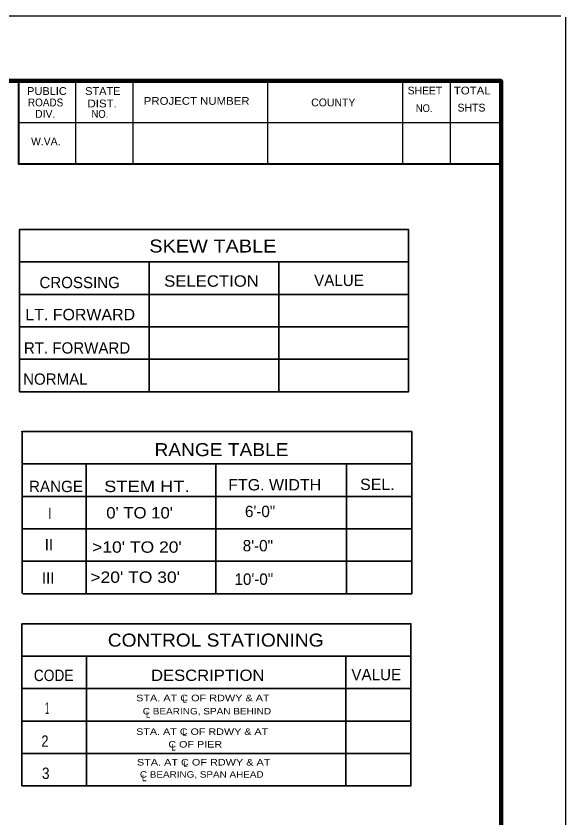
# Model space of a CAD drawing. Extents: x 1.6 to 19.9, y 2.8 to 9.5.
# Drawn here: x 19.239 to 19.901, y 8.58 to 9.545 of the extents above; entities that cross this region are included whole.
import ezdxf
from ezdxf.enums import TextEntityAlignment as Align

# ---------------------------------------------------------------- set-up
doc = ezdxf.new("R2010")
doc.units = 0
doc.header["$LTSCALE"] = 0.0047
doc.layers.add('1', color=7, linetype='Continuous', lineweight=35)

msp = doc.modelspace()

# ---------------------------------------------------------------- linework, layer by layer
at = {"layer": '1', "lineweight": 25}
for p, q in [((19.894917, 9.545083), (16.26675, 9.545083)), ((19.901167, 7.2855), (19.901167, 9.543917)), ((19.3105, 9.467), (19.3105, 9.367)), ((19.37925, 9.467), (19.37925, 9.367)), ((19.54175, 9.467), (19.54175, 9.367)), ((19.70425, 9.467), (19.70425, 9.367)), ((19.76175, 9.467), (19.76175, 9.367)), ((19.24175, 9.417), (19.823, 9.417))]:
    msp.add_line(p, q, dxfattribs=at)
at = {"layer": '1'}
for p, q in [((19.24275, 9.249), (19.7115, 9.249)), ((19.399, 9.09275), (19.399, 9.249667)), ((19.55525, 9.09275), (19.55525, 9.24875)), ((19.24275, 9.21), (19.7115, 9.21)), ((19.24275, 9.170917), (19.7115, 9.170917)), ((19.24275, 9.131833), (19.7115, 9.131833)), ((19.245917, 8.84975), (19.245917, 9.045083)), ((19.246667, 9.045), (19.715417, 9.045)), ((19.715417, 9.045), (19.715417, 8.849667)), ((19.246667, 9.005917), (19.715417, 9.005917)), ((19.323083, 8.849833), (19.323083, 9.00575)), ((19.479333, 8.850333), (19.479333, 9.00625)), ((19.636667, 8.84975), (19.636667, 9.00575)), ((19.246667, 8.966833), (19.715417, 8.966833)), ((19.246667, 8.92775), (19.715417, 8.92775)), ((19.246667, 8.88875), (19.715417, 8.88875)), ((19.7155, 8.8495), (19.24675, 8.8495)), ((19.245583, 8.61825), (19.245583, 8.8135)), ((19.245667, 8.7745), (19.714417, 8.7745)), ((19.323667, 8.61825), (19.323667, 8.774333)), ((19.636167, 8.61825), (19.636167, 8.774333)), ((19.245667, 8.735417), (19.714417, 8.735417)), ((19.245667, 8.696333), (19.714417, 8.696333)), ((19.245667, 8.65725), (19.714417, 8.65725))]:
    msp.add_line(p, q, dxfattribs=at)
at = {"layer": '1', "lineweight": 13}
msp.add_line((19.244917, 9.045), (19.713667, 9.045), dxfattribs=at)
at = {"layer": '1', "lineweight": 106}
msp.add_lwpolyline([(19.823, 7.367), (19.823, 9.467), (16.423, 9.467), (16.423, 7.367)], dxfattribs=at)
at = {"layer": '1', "lineweight": 40}
msp.add_lwpolyline([(19.24175, 9.467), (19.24175, 9.367), (19.823, 9.367)], dxfattribs=at)
at = {"layer": '1'}
msp.add_lwpolyline([(19.24275, 9.09275), (19.24275, 9.288083), (19.7115, 9.288083), (19.7115, 9.09275)], close=True, dxfattribs=at)
msp.add_lwpolyline([(19.245667, 8.8135), (19.714417, 8.8135), (19.714417, 8.61825), (19.245667, 8.61825)], dxfattribs=at)

# ---------------------------------------------------------------- texts
for s, height, width, p in [('PUBLIC', 0.009416, 1.05, (19.275958, 9.450083)), ('STATE', 0.009416, 1.05, (19.34325, 9.450083)), ('TOTAL', 0.009333, 1.1, (19.78825, 9.45075)), ('ROADS', 0.009416, 0.95, (19.274333, 9.436333)), ('DIST.', 0.009416, 1.1, (19.342458, 9.435083)), ('PROJECT NUMBER', 0.009333, 1.1, (19.456292, 9.43825)), ('NO.', 0.009416, 0.9, (19.33975, 9.422583)), ('NO.', 0.009333, 0.9, (19.730375, 9.4295))]:
    msp.add_text(s, height=height, dxfattribs=dict(at, width=width)).set_placement(p, align=Align.CENTER)
for s, height, p in [('SHEET', 0.009333, (19.73125, 9.45075)), ('COUNTY', 0.009416, (19.620875, 9.436333)), ('DIV.', 0.009416, (19.273875, 9.422583)), ('SHTS', 0.009416, (19.787333, 9.430083)), ('W.VA.', 0.009333, (19.274542, 9.3895))]:
    msp.add_text(s, height=height, dxfattribs=at).set_placement(p, align=Align.CENTER)
for s, height, width, p in [('SKEW TABLE', 0.01558, 1.15, (19.39925, 9.260417)), ('SELECTION', 0.01367, 1.1, (19.417167, 9.21925)), ('LT. FORWARD', 0.01367, 1.05, (19.249917, 9.178917)), ('RANGE TABLE', 0.01567, 1.1, (19.4055, 9.01525)), ('FTG. WIDTH', 0.01367, 1.05, (19.494333, 8.974)), ('SEL.', 0.01367, 1.05, (19.653167, 8.9745)), ('STEM HT. ', 0.01375, 1.2, (19.344833, 8.972)), ('I', 0.01358, 0.85, (19.27725, 8.939667)), ("0' TO 10'", 0.01367, 1.1, (19.347417, 8.94025)), (">10' TO 20'", 0.01367, 1.15, (19.330417, 8.899)), (">20' TO 30'", 0.01367, 1.15, (19.32825, 8.86275)), ('CONTROL STATIONING', 0.01567, 1.1, (19.34925, 8.786)), ('CODE', 0.01375, 0.9, (19.260167, 8.7445)), ('DESCRIPTION', 0.01358, 1.1, (19.401417, 8.744667)), ('STA. AT C OF RDWY & AT', 0.007833, 1.25, (19.383417, 8.72025)), ('1', 0.01375, 0.4, (19.273667, 8.705)), ('L', 0.007833, 0.9, (19.439333, 8.7185)), ('C BEARING, SPAN BEHIND', 0.007833, 1.15, (19.391333, 8.704333)), ('L', 0.00775, 0.85, (19.395167, 8.7005)), ('2', 0.01367, 0.85, (19.269167, 8.665417)), ('STA. AT C OF RDWY & AT', 0.00775, 1.25, (19.383417, 8.67975)), ('L', 0.007833, 0.85, (19.439583, 8.6785)), ('C OF PIER', 0.00775, 1.25, (19.422167, 8.6645)), ('L', 0.007833, 0.85, (19.42575, 8.660917)), ('STA. AT C OF RDWY & AT', 0.007833, 1.25, (19.384333, 8.642833)), ('3', 0.01367, 0.9, (19.269917, 8.626667)), ('L', 0.007833, 0.85, (19.440667, 8.640917)), ('C BEARING, SPAN AHEAD', 0.00775, 1.15, (19.387917, 8.62825)), ('L', 0.007833, 0.9, (19.390583, 8.624))]:
    msp.add_text(s, height=height, dxfattribs=dict(at, width=width)).set_placement(p)
for s, height, p in [('CROSSING', 0.01358, (19.266917, 9.2175)), ('VALUE', 0.01367, (19.59775, 9.220083)), ('RT. FORWARD', 0.01358, (19.248167, 9.13875)), ('NORMAL', 0.01358, (19.24725, 9.10125)), ('RANGE', 0.01367, (19.254333, 8.972)), ('6\'-0"', 0.01367, (19.5145, 8.941917)), ('II', 0.01367, (19.27325, 8.901833)), ('8\'-0"', 0.01367, (19.511833, 8.900667)), ('III', 0.01367, (19.269833, 8.861583)), ('10\'-0"', 0.01367, (19.501917, 8.860333)), ('VALUE', 0.01367, (19.642667, 8.7455))]:
    msp.add_text(s, height=height, dxfattribs=at).set_placement(p)

doc.saveas('drawing.dxf')
